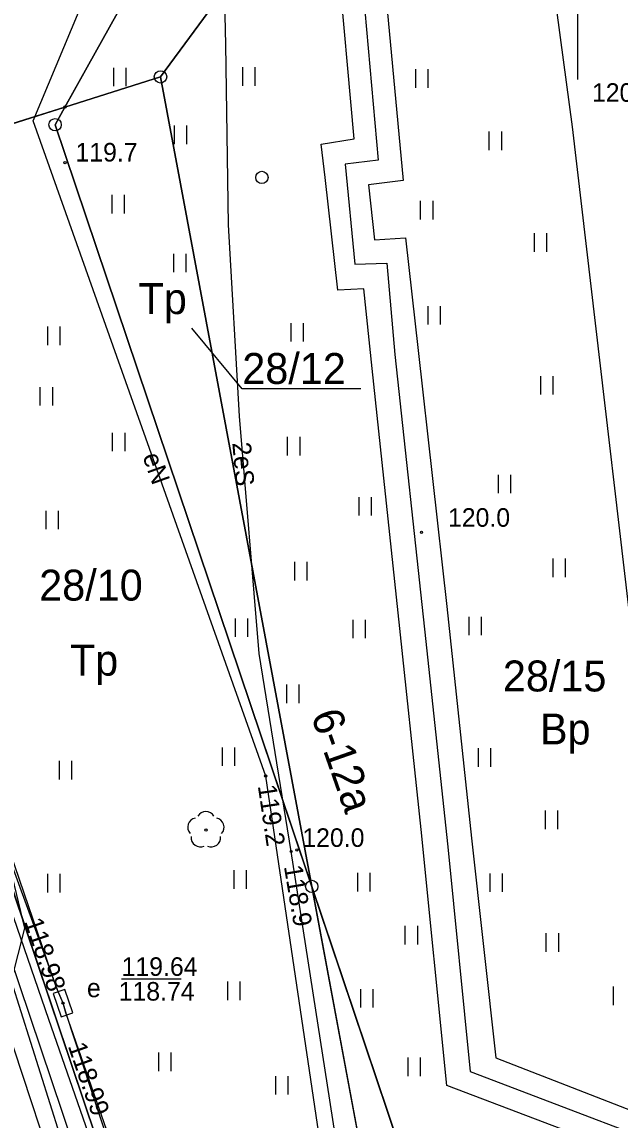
# Model space of a CAD drawing. Extents: x 6432121 to 6432331, y 5662538 to 5662686.
# Drawn here: x 6432277.55 to 6432301.71, y 5662605.46 to 5662649.83 of the extents above; entities that cross this region are included whole.
import ezdxf

# ---------------------------------------------------------------- set-up
doc = ezdxf.new("R2010")
doc.units = 0
for name, color, linetype in [('Warstwa 1', 7, 'Continuous'), ('Warstwa 10', 7, 'Continuous'), ('Warstwa 11', 7, 'Continuous'), ('Warstwa 12', 7, 'Continuous'), ('Warstwa 13', 7, 'Continuous'), ('Warstwa 14', 7, 'Continuous'), ('Warstwa 15', 7, 'Continuous'), ('Warstwa 2', 7, 'Continuous'), ('Warstwa 4', 7, 'Continuous'), ('Warstwa 5', 7, 'Continuous'), ('Warstwa 6', 7, 'Continuous'), ('Warstwa 63', 7, 'Continuous'), ('Warstwa 8', 7, 'Continuous'), ('Warstwa 9', 7, 'Continuous')]:
    doc.layers.add(name, color=color, linetype=linetype)

msp = doc.modelspace()

# ---------------------------------------------------------------- linework, layer by layer
at = {"layer": 'Warstwa 1'}
for p, q in [((6432283.15, 5662647.61), (6432293.88, 5662662.18)), ((6432283.15, 5662647.61), (6432293.88, 5662662.18)), ((6432279.29, 5662646.39), (6432287.724, 5662661.523)), ((6432279.29, 5662646.39), (6432287.724, 5662661.523)), ((6432279.29, 5662646.39), (6432283.15, 5662647.61)), ((6432279.29, 5662646.39), (6432283.15, 5662647.61)), ((6432283.15, 5662647.61), (6432289.26, 5662614.9)), ((6432283.15, 5662647.61), (6432289.26, 5662614.9)), ((6432267.75, 5662642.76), (6432279.29, 5662646.39)), ((6432267.75, 5662642.76), (6432279.29, 5662646.39)), ((6432278.892, 5662645.679), (6432279.29, 5662646.39)), ((6432278.892, 5662645.679), (6432279.29, 5662646.39)), ((6432278.892, 5662645.679), (6432289.26, 5662614.9)), ((6432278.892, 5662645.679), (6432289.26, 5662614.9)), ((6432267.75, 5662642.76), (6432287.64, 5662583.69)), ((6432267.75, 5662642.76), (6432287.64, 5662583.69)), ((6432289.26, 5662614.9), (6432303.776, 5662571.783)), ((6432289.26, 5662614.9), (6432295.88, 5662579.43)), ((6432289.26, 5662614.9), (6432295.88, 5662579.43)), ((6432289.26, 5662614.9), (6432303.776, 5662571.783))]:
    msp.add_line(p, q, dxfattribs=at)
msp.add_circle((6432287.246, 5662643.548), 0.25, dxfattribs=at)
at = {"layer": 'Warstwa 10'}
msp.add_lwpolyline([(6432296.79, 5662556.053), (6432296.201, 5662561.437), (6432295.017, 5662573.011), (6432294.553, 5662576.918), (6432292.907, 5662587.574), (6432290.887, 5662600.464), (6432288.429, 5662616.311), (6432287.139, 5662624.307), (6432286.336, 5662633.904), (6432285.897, 5662641.637), (6432285.792, 5662648.915), (6432285.649, 5662654.781), (6432285.519, 5662656.344), (6432285.415, 5662656.517), (6432289.838, 5662661.556), (6432292.019, 5662663.878), (6432295.895, 5662667.79), (6432302.762, 5662670.351), (6432309.086, 5662672.408), (6432310.267, 5662672.779), (6432314.604, 5662673.152), (6432325.606, 5662675.971), (6432325.976, 5662676.047)], dxfattribs=at)
for centre in [(6432283.15, 5662647.61), (6432278.892, 5662645.679), (6432289.26, 5662614.9)]:
    msp.add_circle(centre, 0.25, dxfattribs=at)
at = {"layer": 'Warstwa 11'}
msp.add_circle((6432284.984, 5662617.178), 0.05, dxfattribs=at)
for centre, start, end in [((6432284.984, 5662617.553), 30.1471, 149.8529), ((6432284.627, 5662617.294), 102.1471, 221.8529), ((6432285.341, 5662617.294), 318.1471, 77.8529), ((6432284.764, 5662616.875), 174.1471, 293.8529), ((6432285.204, 5662616.875), 246.1471, 5.8529)]:
    msp.add_arc(centre, 0.375, start, end, dxfattribs=at)
at = {"layer": 'Warstwa 12'}
for points in [[(6432259.267, 5662681.053), (6432259.329, 5662671.143), (6432259.331, 5662662.919), (6432260.078, 5662660.682), (6432263.877, 5662649.208), (6432267.527, 5662638.022), (6432271.438, 5662626.054), (6432273.548, 5662619.652), (6432276.516, 5662610.473), (6432279.664, 5662600.926), (6432282.613, 5662591.736), (6432284.976, 5662585.268), (6432286.395, 5662580.459), (6432288.268, 5662574.665)], [(6432288.269, 5662573.47), (6432290.18, 5662576.365), (6432289.651, 5662577.89), (6432283.657, 5662595.089), (6432278.636, 5662609.529), (6432275.228, 5662619.384), (6432273.259, 5662625.008), (6432269.06, 5662637.307), (6432265.455, 5662647.676), (6432262.131, 5662657.28), (6432261.494, 5662659.216), (6432262.228, 5662660.626), (6432262.598, 5662661.472), (6432263.21, 5662662.431), (6432263.592, 5662662.793), (6432265.636, 5662665.038), (6432264.282, 5662671.637), (6432263.631, 5662675.181), (6432263.032, 5662678.117), (6432262.911, 5662681.053)], [(6432295.301, 5662556.053), (6432293.38, 5662579.05), (6432287.4, 5662619.36), (6432278, 5662645.83), (6432280.48, 5662651.78), (6432284.95, 5662659.55), (6432287.83, 5662661.59), (6432289.41, 5662662.88), (6432294.04, 5662666.15), (6432294.57, 5662666.58), (6432295.66, 5662667.86), (6432303.71, 5662670.68), (6432307.18, 5662671.52), (6432309.43, 5662672.69), (6432315.26, 5662674.17), (6432317.7, 5662674.35), (6432325.976, 5662676.304)], [(6432304.101, 5662656.637), (6432302.607, 5662655.419), (6432299.133, 5662654.283), (6432298.805, 5662653.778), (6432298.784, 5662653.031), (6432299.783, 5662645.591), (6432302.993, 5662618.112), (6432305.344, 5662594.292), (6432309.869, 5662577.925), (6432310.42, 5662573.418), (6432310.299, 5662572.714), (6432309.996, 5662572.066), (6432304.851, 5662562.867), (6432301.278, 5662556.053)], [(6432290.708, 5662655.216), (6432291.2, 5662652.55), (6432291.943, 5662644.25), (6432290.61, 5662644.078), (6432291.004, 5662640.039), (6432292.296, 5662640.09), (6432292.613, 5662636.397), (6432293.809, 5662625.295), (6432294.764, 5662616.494), (6432295.661, 5662607.42), (6432306.342, 5662603.354), (6432315.232, 5662599.893), (6432316.512, 5662599.405), (6432317.845, 5662599.056), (6432325.976, 5662596.135)], [(6432294.644, 5662569.974), (6432292.199, 5662571.213), (6432291.73, 5662571.359), (6432291.554, 5662571.691), (6432290.843, 5662575.72), (6432287.011, 5662587.057), (6432285.41, 5662591.097), (6432281.352, 5662603.627), (6432279.346, 5662609.722), (6432279.211, 5662610.184), (6432279.026, 5662610.616), (6432274.158, 5662623.936), (6432272.237, 5662630.449), (6432265.984, 5662647.596), (6432266.37, 5662648.378)], [(6432291.73, 5662571.359), (6432291.68, 5662571.75), (6432289.74, 5662579), (6432288.94, 5662582.19), (6432279.33, 5662609.79), (6432279.211, 5662610.184), (6432278.94, 5662610.85), (6432266.32, 5662647.75), (6432266.37, 5662648.378)], [(6432273.378, 5662628.56), (6432274.214, 5662626.373), (6432275.936, 5662621.592), (6432276.137, 5662621.121), (6432277.158, 5662615.29), (6432277.656, 5662613.21), (6432277.121, 5662611.091), (6432279.065, 5662604.892), (6432281.714, 5662603.797), (6432281.489, 5662600.828), (6432283.129, 5662594.282), (6432283.903, 5662591.502), (6432284.529, 5662588.89)]]:
    msp.add_lwpolyline(points, dxfattribs=at)
msp.add_circle((6432279.29, 5662646.39), 0.045, dxfattribs=at)
at = {"layer": 'Warstwa 13'}
for centre in [(6432279.293, 5662644.144), (6432293.693, 5662629.209), (6432288.658, 5662616.375)]:
    msp.add_circle(centre, 0.045, dxfattribs=at)
at = {"layer": 'Warstwa 14'}
msp.add_line((6432281.579, 5662611.162), (6432283.98, 5662611.162), dxfattribs=at)
for centre in [(6432287.4, 5662619.36), (6432288.429, 5662616.311), (6432279.211, 5662610.184), (6432279.211, 5662610.184), (6432279.211, 5662610.184), (6432279.211, 5662610.184)]:
    msp.add_circle(centre, 0.045, dxfattribs=at)
at = {"layer": 'Warstwa 15'}
msp.add_lwpolyline([(6432291.246, 5662635), (6432286.453, 5662635), (6432284.409, 5662637.453)], dxfattribs=at)
at = {"layer": 'Warstwa 4'}
msp.add_lwpolyline([(6432279.609, 5662609.792), (6432279.286, 5662610.738), (6432278.813, 5662610.576), (6432279.136, 5662609.63)], close=True, dxfattribs=at)
at = {"layer": 'Warstwa 5'}
for p, q in [((6432278.892, 5662645.679), (6432287.059, 5662660.33)), ((6432278.892, 5662645.679), (6432287.059, 5662660.33)), ((6432281.264, 5662647.23), (6432281.264, 5662647.98)), ((6432281.764, 5662647.23), (6432281.764, 5662647.98)), ((6432286.479, 5662647.254), (6432286.479, 5662648.004)), ((6432286.979, 5662647.254), (6432286.979, 5662648.004)), ((6432293.459, 5662647.17), (6432293.459, 5662647.92)), ((6432293.959, 5662647.17), (6432293.959, 5662647.92)), ((6432278.892, 5662645.679), (6432299.828, 5662583.507)), ((6432278.892, 5662645.679), (6432299.828, 5662583.507)), ((6432283.711, 5662644.897), (6432283.711, 5662645.647)), ((6432284.211, 5662644.897), (6432284.211, 5662645.647)), ((6432296.434, 5662644.654), (6432296.434, 5662645.404)), ((6432296.934, 5662644.654), (6432296.934, 5662645.404)), ((6432281.202, 5662642.094), (6432281.202, 5662642.844)), ((6432281.702, 5662642.094), (6432281.702, 5662642.844)), ((6432293.66, 5662641.854), (6432293.66, 5662642.604)), ((6432294.16, 5662641.854), (6432294.16, 5662642.604)), ((6432298.254, 5662640.54), (6432298.254, 5662641.29)), ((6432298.754, 5662640.54), (6432298.754, 5662641.29)), ((6432283.691, 5662639.717), (6432283.691, 5662640.467)), ((6432284.191, 5662639.717), (6432284.191, 5662640.467)), ((6432293.962, 5662637.6), (6432293.962, 5662638.35)), ((6432294.462, 5662637.6), (6432294.462, 5662638.35)), ((6432278.602, 5662636.772), (6432278.602, 5662637.522)), ((6432279.102, 5662636.772), (6432279.102, 5662637.522)), ((6432288.43, 5662636.914), (6432288.43, 5662637.664)), ((6432288.93, 5662636.914), (6432288.93, 5662637.664)), ((6432298.515, 5662634.773), (6432298.515, 5662635.523)), ((6432299.015, 5662634.773), (6432299.015, 5662635.523)), ((6432278.295, 5662634.33), (6432278.295, 5662635.08)), ((6432278.795, 5662634.33), (6432278.795, 5662635.08)), ((6432281.217, 5662632.485), (6432281.217, 5662633.235)), ((6432281.717, 5662632.485), (6432281.717, 5662633.235)), ((6432288.286, 5662632.311), (6432288.286, 5662633.061)), ((6432288.786, 5662632.311), (6432288.786, 5662633.061)), ((6432296.802, 5662630.788), (6432296.802, 5662631.538)), ((6432297.302, 5662630.788), (6432297.302, 5662631.538)), ((6432291.172, 5662629.885), (6432291.172, 5662630.635)), ((6432291.672, 5662629.885), (6432291.672, 5662630.635)), ((6432271.072, 5662629.787), (6432281.622, 5662598.544)), ((6432278.528, 5662629.33), (6432278.528, 5662630.08)), ((6432279.028, 5662629.33), (6432279.028, 5662630.08)), ((6432288.578, 5662627.26), (6432288.578, 5662628.01)), ((6432289.078, 5662627.26), (6432289.078, 5662628.01)), ((6432299.009, 5662627.399), (6432299.009, 5662628.149)), ((6432299.509, 5662627.399), (6432299.509, 5662628.149)), ((6432286.181, 5662624.98), (6432286.181, 5662625.73)), ((6432286.681, 5662624.98), (6432286.681, 5662625.73)), ((6432295.622, 5662625.049), (6432295.622, 5662625.799)), ((6432296.122, 5662625.049), (6432296.122, 5662625.799)), ((6432290.936, 5662624.929), (6432290.936, 5662625.679)), ((6432291.436, 5662624.929), (6432291.436, 5662625.679)), ((6432288.252, 5662622.305), (6432288.252, 5662623.055)), ((6432288.752, 5662622.305), (6432288.752, 5662623.055)), ((6432285.659, 5662619.769), (6432285.659, 5662620.519)), ((6432286.159, 5662619.769), (6432286.159, 5662620.519)), ((6432295.999, 5662619.732), (6432295.999, 5662620.482)), ((6432296.499, 5662619.732), (6432296.499, 5662620.482)), ((6432279.07, 5662619.223), (6432279.07, 5662619.973)), ((6432279.57, 5662619.223), (6432279.57, 5662619.973)), ((6432298.708, 5662617.22), (6432298.708, 5662617.97)), ((6432299.208, 5662617.22), (6432299.208, 5662617.97)), ((6432286.129, 5662614.804), (6432286.129, 5662615.554)), ((6432286.629, 5662614.804), (6432286.629, 5662615.554)), ((6432278.602, 5662614.653), (6432278.602, 5662615.403)), ((6432279.102, 5662614.653), (6432279.102, 5662615.403)), ((6432291.121, 5662614.7), (6432291.121, 5662615.45)), ((6432291.621, 5662614.7), (6432291.621, 5662615.45)), ((6432296.467, 5662614.679), (6432296.467, 5662615.429)), ((6432296.967, 5662614.679), (6432296.967, 5662615.429)), ((6432293.039, 5662612.552), (6432293.039, 5662613.302)), ((6432293.539, 5662612.552), (6432293.539, 5662613.302)), ((6432298.736, 5662612.26), (6432298.736, 5662613.01)), ((6432299.236, 5662612.26), (6432299.236, 5662613.01)), ((6432285.874, 5662610.304), (6432285.874, 5662611.054)), ((6432286.374, 5662610.304), (6432286.374, 5662611.054)), ((6432291.24, 5662610.005), (6432291.24, 5662610.755)), ((6432291.74, 5662610.005), (6432291.74, 5662610.755)), ((6432301.45, 5662610.102), (6432301.45, 5662610.852)), ((6432283.087, 5662607.435), (6432283.087, 5662608.185)), ((6432283.587, 5662607.435), (6432283.587, 5662608.185)), ((6432293.152, 5662607.237), (6432293.152, 5662607.987)), ((6432293.652, 5662607.237), (6432293.652, 5662607.987)), ((6432287.812, 5662606.49), (6432287.812, 5662607.24)), ((6432288.312, 5662606.49), (6432288.312, 5662607.24))]:
    msp.add_line(p, q, dxfattribs=at)
at = {"layer": 'Warstwa 6'}
for points in [[(6432268.232, 5662654.789), (6432266.742, 5662645.747), (6432267.75, 5662642.76), (6432279.29, 5662646.39), (6432287.724, 5662661.523), (6432302.18, 5662664.8), (6432302.345, 5662664.846), (6432301.273, 5662669.629)], [(6432287.724, 5662661.523), (6432279.29, 5662646.39), (6432283.15, 5662647.61), (6432293.88, 5662662.18), (6432302.18, 5662664.8)], [(6432283.15, 5662647.61), (6432279.29, 5662646.39), (6432278.892, 5662645.679), (6432289.26, 5662614.9)], [(6432278.892, 5662645.679), (6432279.29, 5662646.39), (6432267.75, 5662642.76), (6432287.64, 5662583.69), (6432294.025, 5662578.332), (6432295.024, 5662576.599), (6432295.196, 5662575.127), (6432301.46, 5662572.69), (6432295.88, 5662579.43), (6432289.26, 5662614.9)], [(6432289.26, 5662614.9), (6432303.776, 5662571.783), (6432301.46, 5662572.69), (6432295.88, 5662579.43)]]:
    msp.add_lwpolyline(points, close=True, dxfattribs=at)
for points in [[(6432325.976, 5662612.948), (6432316.1, 5662616.8), (6432316.08, 5662616.73), (6432312.24, 5662618.23), (6432309.49, 5662630.11), (6432302.18, 5662664.8), (6432293.88, 5662662.18), (6432283.15, 5662647.61), (6432289.26, 5662614.9), (6432303.776, 5662571.783), (6432317.37, 5662566.48), (6432324.02, 5662582.95), (6432324.37, 5662582.84), (6432325.976, 5662586.89)], [(6432295.199, 5662556.053), (6432289.811, 5662577.223), (6432287.64, 5662583.69), (6432267.75, 5662642.76), (6432246.69, 5662636.13), (6432263.163, 5662588.197), (6432269.007, 5662560.534), (6432269.756, 5662556.053)]]:
    msp.add_lwpolyline(points, dxfattribs=at)
at = {"layer": 'Warstwa 63'}
msp.add_line((6432300, 5662652.5), (6432300, 5662647.5), dxfattribs=at)
at = {"layer": 'Warstwa 8'}
msp.add_lwpolyline([(6432290.313, 5662652.447), (6432292.087, 5662652.653), (6432292.956, 5662643.422), (6432291.555, 5662643.251), (6432291.798, 5662641.022), (6432293.049, 5662641.114), (6432293.559, 5662636.56), (6432294.723, 5662626.21), (6432295.711, 5662616.845), (6432296.69, 5662607.978), (6432304.075, 5662605.107), (6432315.519, 5662600.715), (6432314.944, 5662599.073), (6432305.744, 5662602.672), (6432294.713, 5662606.863), (6432293.683, 5662617.204), (6432292.756, 5662625.951), (6432291.694, 5662635.829), (6432291.37, 5662639.051), (6432290.32, 5662638.997), (6432289.798, 5662643.552), (6432289.64, 5662644.893), (6432290.973, 5662645.106)], close=True, dxfattribs=at)
at = {"layer": 'Warstwa 9'}
msp.add_line((6432271.072, 5662629.787), (6432281.622, 5662598.544), dxfattribs=at)

# ---------------------------------------------------------------- texts
at = {"layer": 'Warstwa 11'}
msp.add_text('2eS', height=0.75, rotation=274.7848, dxfattribs=at).set_placement((6432286.05, 5662632.827))
at = {"layer": 'Warstwa 13'}
for s, p in [('120.1', (6432300.58, 5662646.604)), ('119.7', (6432279.714, 5662644.192)), ('120.0', (6432294.763, 5662629.434)), ('120.0', (6432288.879, 5662616.498))]:
    msp.add_text(s, height=0.75, dxfattribs=at).set_placement(p)
msp.add_text('eN', height=0.75, rotation=289.55, dxfattribs=at).set_placement((6432282.414, 5662632.281))
at = {"layer": 'Warstwa 14'}
for s, height, rotation, p in [('6-12a', 1.25, 289.3036, (6432289.215, 5662621.816)), ('119.2', 0.75, 278.4403, (6432287.079, 5662618.963)), ('118.9', 0.75, 279.5117, (6432288.132, 5662615.707)), ('118.98', 0.75, 288.8796, (6432277.642, 5662613.489)), ('118.99', 0.75, 289.1947, (6432279.398, 5662608.454))]:
    msp.add_text(s, height=height, rotation=rotation, dxfattribs=at).set_placement(p)
msp.add_text('118.74', height=0.75, dxfattribs=at).set_placement((6432281.459, 5662610.287))
at = {"layer": 'Warstwa 15'}
for s, height, p in [('28/12', 1.25, (6432286.454, 5662635.204)), ('28/10', 1.25, (6432278.249, 5662626.45)), ('28/15', 1.25, (6432296.981, 5662622.779)), ('119.64', 0.75, (6432281.578, 5662611.287))]:
    msp.add_text(s, height=height, dxfattribs=at).set_placement(p)
at = {"layer": 'Warstwa 2'}
for s, p in [('Tp', (6432282.263, 5662638.027)), ('Tp', (6432279.49, 5662623.418)), ('Bp', (6432298.479, 5662620.636))]:
    msp.add_text(s, height=1.25, dxfattribs=at).set_placement(p)
at = {"layer": 'Warstwa 5'}
msp.add_text('e', height=0.75, dxfattribs=at).set_placement((6432280.178, 5662610.425))

doc.saveas('drawing.dxf')
